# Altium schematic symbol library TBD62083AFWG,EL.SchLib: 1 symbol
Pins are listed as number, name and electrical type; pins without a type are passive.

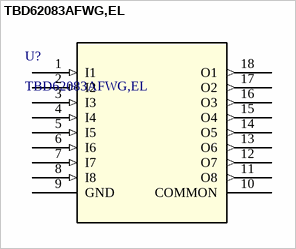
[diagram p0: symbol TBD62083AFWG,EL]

## TBD62083AFWG,EL
designator U?
Description; Manufacturer_Name: Toshiba Electronic Devices & Storage Corp.
footprint P-SOP18-0812-1p27-001_TOS
pins: 1 I1 (in), 2 I2 (in), 3 I3 (in), 4 I4 (in), 5 I5 (in), 6 I6 (in), 7 I7 (in), 8 I8 (in), 9 GND (power), 10 COMMON, 11 O8 (out), 12 O7 (out), 13 O6 (out), 14 O5 (out), 15 O4 (out), 16 O3 (out), 17 O2 (out), 18 O1 (out)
